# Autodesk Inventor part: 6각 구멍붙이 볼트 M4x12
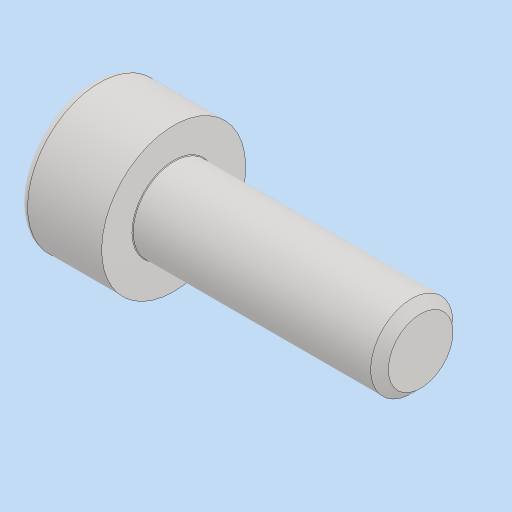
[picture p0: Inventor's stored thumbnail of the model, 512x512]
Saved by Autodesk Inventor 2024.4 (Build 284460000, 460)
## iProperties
Created: 2026-08
Part Number: 6각 구멍붙이 볼트 M4x12
Material: 스테인리스강
Description: 6각 소켓 머리 캡 나사
Document SubType Name: Modeling
Designer: home
Density: 8.08 g/cm^3
Appearance: 기본값
Author: jhkim
Sending System: Autodesk Inventor 2027
Preprocessor: ST-DEVELOPER v20.1
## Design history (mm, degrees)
feature "Solid1"
node "솔리드1"
